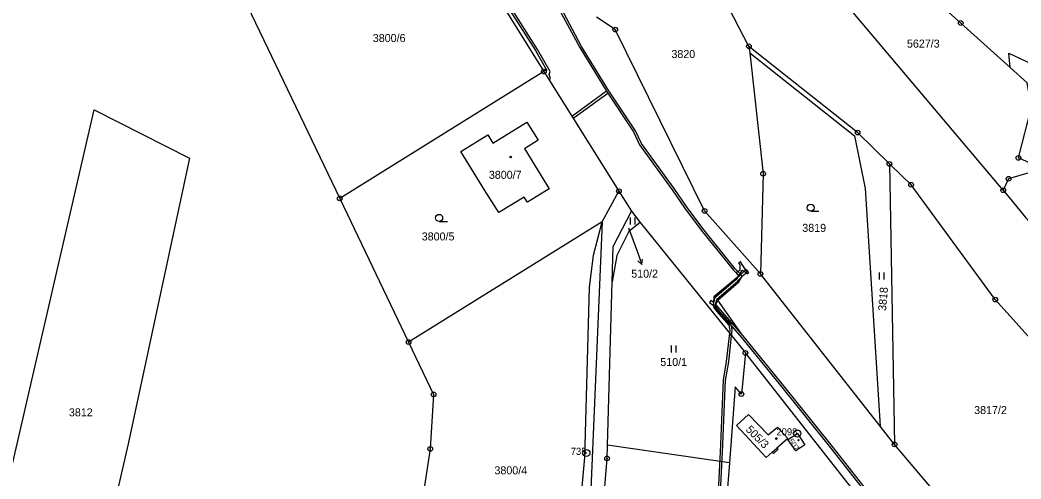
# Model space of a CAD drawing. Extents: x -644096 to -634268, y -1141430 to -1133463.
# Drawn here: x -640699.8 to -640487.2, y -1137603.8 to -1137506.2 of the extents above; entities that cross this region are included whole.
import ezdxf

# ---------------------------------------------------------------- set-up
doc = ezdxf.new("R2010")
doc.units = 0
for name, color, linetype in [('_CIVIL_CONSTRUCTION', 7, 'Continuous'), ('B_Hranice _3D', 7, 'Continuous'), ('M_Svah_Nasyp', 7, 'Continuous'), ('M_Svah_Zarez', 7, 'Continuous'), ('svrsek_osa_sjezdy', 7, 'Continuous'), ('svrsek_osa_VRT', 7, 'Continuous'), ('svrsek_popisy_VRT', 7, 'Continuous'), ('terminal_VRT', 7, 'Continuous')]:
    doc.layers.add(name, color=color, linetype=linetype)

msp = doc.modelspace()

# ---------------------------------------------------------------- linework, layer by layer
at = {"layer": '_CIVIL_CONSTRUCTION'}
for centre, radius in [((-640499.97, -1137506.88), 0.5), ((-640499.97, -1137506.88), 0.0303), ((-640573.37, -1137508.28), 0.5), ((-640573.37, -1137508.28), 0.0303), ((-640544.96, -1137511.84), 0.5), ((-640544.96, -1137511.84), 0.0303), ((-640588.52, -1137517.2), 0.5), ((-640588.52, -1137517.2), 0.0303), ((-640521.87, -1137530.18), 0.5), ((-640521.87, -1137530.18), 0.0303), ((-640515.13, -1137536.84), 0.5), ((-640515.13, -1137536.84), 0.0303), ((-640487.72, -1137535.55), 0.5), ((-640487.72, -1137535.55), 0.0303), ((-640541.95, -1137538.94), 0.5), ((-640541.95, -1137538.94), 0.0303), ((-640510.51, -1137541.27), 0.5), ((-640489.79, -1137539.99), 0.5), ((-640489.79, -1137539.99), 0.0303), ((-640572.6, -1137542.65), 0.5), ((-640572.6, -1137542.65), 0.0303), ((-640510.51, -1137541.27), 0.0303), ((-640490.94, -1137542.42), 0.5), ((-640490.94, -1137542.42), 0.0303), ((-640631.9, -1137544.15), 0.5), ((-640631.9, -1137544.15), 0.0303), ((-640554.39, -1137546.81), 0.5), ((-640554.39, -1137546.81), 0.0303), ((-640542.54, -1137560.2), 0.5), ((-640542.54, -1137560.2), 0.0303), ((-640492.62, -1137565.68), 0.5), ((-640492.62, -1137565.68), 0.0303), ((-640617.3, -1137574.69), 0.5), ((-640617.3, -1137574.69), 0.0303), ((-640545.72, -1137577), 0.5), ((-640545.72, -1137577), 0.0303), ((-640611.98, -1137585.82), 0.5), ((-640546.55, -1137585.75), 0.5), ((-640546.55, -1137585.75), 0.0303), ((-640611.98, -1137585.82), 0.0303), ((-640534.68, -1137594.14), 0.75), ((-640534.68, -1137594.14), 0.03), ((-640514.01, -1137596.46), 0.5), ((-640612.67, -1137597.4), 0.5), ((-640612.67, -1137597.4), 0.0303), ((-640579.49, -1137598.29), 0.75), ((-640579.49, -1137598.29), 0.03), ((-640514.01, -1137596.46), 0.0303), ((-640575.12, -1137599.42), 0.5), ((-640575.12, -1137599.42), 0.0303)]:
    msp.add_circle(centre, radius, dxfattribs=at)
at = {"layer": 'B_Hranice _3D'}
for points in [[(-640595.71, -1137504.26), (-640590.32, -1137512.76), (-640587.9, -1137517), (-640588.49, -1137517.02), (-640588.52, -1137517.2), (-640587.46, -1137518.9), (-640587.15, -1137518.7), (-640587.38, -1137517.83), (-640587.22, -1137517.16), (-640589.9, -1137512.5), (-640595.29, -1137504)], [(-640585.37, -1137503.86), (-640580.93, -1137512.11), (-640575.25, -1137521.39), (-640569.53, -1137530.02), (-640568.24, -1137532.75), (-640561.3, -1137542.31), (-640558.63, -1137546.18), (-640555.11, -1137550.91), (-640548.25, -1137559.45), (-640547.06, -1137560.64), (-640552.46, -1137565.07), (-640552.53, -1137566.28), (-640552.47, -1137566.95), (-640552.43, -1137567.35), (-640551.88, -1137568.14), (-640549.22, -1137571.12), (-640549.01, -1137572.18), (-640549.08, -1137572.82), (-640548.65, -1137573.37), (-640548.51, -1137572.16), (-640548.68, -1137571.29), (-640546.92, -1137573.3), (-640538.57, -1137583.56), (-640527.63, -1137597.19), (-640517.52, -1137610.05)], [(-640585.37, -1137503.86), (-640580.93, -1137512.11), (-640575.25, -1137521.39), (-640582.37, -1137526.58), (-640582.57, -1137526.7), (-640582.31, -1137527.12), (-640582.11, -1137527), (-640574.98, -1137521.82), (-640569.53, -1137530.02), (-640568.24, -1137532.75), (-640561.3, -1137542.31), (-640558.63, -1137546.18), (-640555.11, -1137550.91), (-640548.25, -1137559.45), (-640547.06, -1137560.64), (-640552.46, -1137565.07), (-640552.53, -1137566.28), (-640553.06, -1137565.86), (-640553.36, -1137566.26), (-640552.47, -1137566.95), (-640546.92, -1137573.3), (-640538.57, -1137583.56), (-640527.63, -1137597.19), (-640517.52, -1137610.05)], [(-640517.12, -1137609.75), (-640527.23, -1137596.89), (-640538.19, -1137583.24), (-640546.54, -1137572.98), (-640551.59, -1137565.77), (-640547.1, -1137561.88), (-640546.49, -1137560.82), (-640546.68, -1137560.31), (-640547.87, -1137559.13), (-640554.73, -1137550.59), (-640558.21, -1137545.9), (-640560.88, -1137542.03), (-640567.8, -1137532.49), (-640569.09, -1137529.78), (-640574.71, -1137521.33), (-640580.51, -1137511.85), (-640584.95, -1137503.6)], [(-640545.67, -1137559.38), (-640546.68, -1137560.31), (-640547.87, -1137559.13), (-640554.73, -1137550.59), (-640558.21, -1137545.9), (-640560.88, -1137542.03), (-640567.8, -1137532.49), (-640569.09, -1137529.78), (-640574.71, -1137521.33), (-640580.51, -1137511.85), (-640584.95, -1137503.6)], [(-640487.06, -1137645.3), (-640489.13, -1137643.47), (-640490.6, -1137641.59), (-640491.45, -1137640.46), (-640491.86, -1137640.27), (-640496.56, -1137634.97), (-640498.35, -1137634.11), (-640504.46, -1137627.49), (-640505.83, -1137625.5), (-640506.65, -1137624.49), (-640511.27, -1137618.95), (-640512.5, -1137617.22), (-640513.41, -1137614.17), (-640514.94, -1137612.71), (-640517.12, -1137609.75), (-640527.23, -1137596.89), (-640538.19, -1137583.24), (-640546.54, -1137572.98), (-640552.01, -1137566.72), (-640551.59, -1137565.77), (-640547.1, -1137561.88), (-640546.49, -1137560.82), (-640545.33, -1137559.74), (-640545.67, -1137559.38)]]:
    msp.add_lwpolyline(points, dxfattribs=at)
for points in [[(-640545.01, -1137559.9), (-640545.33, -1137559.46), (-640545.77, -1137559.17), (-640546.73, -1137557.63), (-640547.15, -1137557.89), (-640546.92, -1137558.26), (-640546.89, -1137559.52), (-640547.66, -1137559.93), (-640547.48, -1137560.26), (-640547.12, -1137560.52), (-640546.31, -1137559.41), (-640545.68, -1137559.83), (-640545.42, -1137560.19)], [(-640545.67, -1137559.38), (-640547.49, -1137561.13), (-640547.74, -1137561.47), (-640552.27, -1137565.34), (-640552.56, -1137566.77), (-640552.43, -1137567.35), (-640551.88, -1137568.14), (-640549.22, -1137571.12), (-640549.01, -1137572.18), (-640549.08, -1137572.82), (-640548.65, -1137573.37), (-640548.51, -1137572.16), (-640548.76, -1137570.88), (-640551.48, -1137567.82), (-640551.97, -1137567.15), (-640552.04, -1137566.77), (-640551.81, -1137565.6), (-640547.38, -1137561.81), (-640547.11, -1137561.47), (-640545.33, -1137559.74)], [(-640549.77, -1137578.81), (-640550.43, -1137582.83), (-640551.07, -1137598.09), (-640551.86, -1137613.51), (-640556.82, -1137647.62), (-640558.57, -1137666.41), (-640560, -1137686.48), (-640560.91, -1137694.7), (-640563.67, -1137695.47), (-640576.51, -1137693.45), (-640575.72, -1137694.09), (-640563.65, -1137695.99), (-640560.45, -1137695.1), (-640559.5, -1137686.52), (-640558.07, -1137666.45), (-640556.32, -1137647.68), (-640551.36, -1137613.55), (-640550.57, -1137598.11), (-640549.93, -1137582.89), (-640549.27, -1137578.87), (-640548.65, -1137573.37), (-640549.08, -1137572.82)]]:
    msp.add_lwpolyline(points, close=True, dxfattribs=at)
at = {"layer": 'M_Svah_Nasyp'}
msp.add_line((-640540.02, -1137598.09), (-640539.02, -1137597.22), dxfattribs=at)
at = {"layer": 'M_Svah_Zarez'}
for centre, radius in [((-640595.58, -1137535.37), 0.175), ((-640539.14, -1137595.2), 0.175), ((-640534.43, -1137595.54), 0.117)]:
    msp.add_circle(centre, radius, dxfattribs=at)
at = {"layer": 'svrsek_osa_sjezdy'}
for p, q in [((-640531.85, -1137546.89), (-640530.1, -1137546.89)), ((-640610.8, -1137549.05), (-640609.05, -1137549.05)), ((-640570.16, -1137549.74), (-640570.16, -1137548.24)), ((-640569.16, -1137549.74), (-640569.16, -1137548.24)), ((-640517.24, -1137561.42), (-640517.24, -1137559.92)), ((-640516.24, -1137561.42), (-640516.24, -1137559.92)), ((-640561.43, -1137576.91), (-640561.43, -1137575.41)), ((-640560.43, -1137576.91), (-640560.43, -1137575.41))]:
    msp.add_line(p, q, dxfattribs=at)
for centre in [(-640531.85, -1137546.14), (-640610.8, -1137548.3)]:
    msp.add_circle(centre, 0.75, dxfattribs=at)
at = {"layer": 'svrsek_popisy_VRT'}
for p, q in [((-640570.57, -1137550.45), (-640568.75, -1137555.37)), ((-640568.75, -1137555.37), (-640567.72, -1137558.19)), ((-640567.72, -1137558.19), (-640568.54, -1137557.42)), ((-640567.72, -1137558.19), (-640567.6, -1137557.08))]:
    msp.add_line(p, q, dxfattribs=at)
at = {"layer": 'terminal_VRT'}
for p, q in [((-640490.94, -1137542.42), (-640547.2, -1137475.72)), ((-640652.7, -1137500.65), (-640631.9, -1137544.15)), ((-640544.96, -1137511.84), (-640544.81, -1137513.24)), ((-640588.52, -1137517.2), (-640631.9, -1137544.15)), ((-640588.52, -1137517.2), (-640572.6, -1137542.65)), ((-640515.13, -1137536.84), (-640514.01, -1137596.46)), ((-640576.13, -1137549.11), (-640572.6, -1137542.65)), ((-640572.6, -1137542.65), (-640569.95, -1137546.91)), ((-640631.9, -1137544.15), (-640617.3, -1137574.69)), ((-640569.95, -1137546.91), (-640568.05, -1137549.26)), ((-640576.13, -1137549.11), (-640617.3, -1137574.69)), ((-640568.05, -1137549.26), (-640545.72, -1137577)), ((-640517.08, -1137592.55), (-640542.54, -1137560.2)), ((-640575.04, -1137596.64), (-640574.04, -1137561.9)), ((-640512.3, -1137619.49), (-640545.72, -1137577)), ((-640514.01, -1137596.46), (-640517.08, -1137592.55)), ((-640549.1, -1137600.38), (-640575.04, -1137596.64)), ((-640497.09, -1137616.4), (-640514.01, -1137596.46))]:
    msp.add_line(p, q, dxfattribs=at)
for points in [[(-640544.96, -1137511.84), (-640554.31, -1137493.73), (-640565.75, -1137475.24), (-640568.46, -1137472.15)], [(-640614.14, -1137476.23), (-640607.29, -1137488.59), (-640605.78, -1137489.49), (-640588.52, -1137517.2)], [(-640515.72, -1137492.72), (-640499.97, -1137506.88), (-640489.47, -1137516.32)], [(-640542.54, -1137560.2), (-640554.39, -1137546.81), (-640573.37, -1137508.28), (-640577.39, -1137505.61)], [(-640515.13, -1137536.84), (-640521.87, -1137530.18), (-640544.96, -1137511.84)], [(-640544.81, -1137513.24), (-640522.57, -1137530.89), (-640520.26, -1137542.03), (-640517.08, -1137592.55)], [(-640544.81, -1137513.24), (-640541.95, -1137538.94), (-640542.54, -1137560.2)], [(-640489.47, -1137516.32), (-640489.75, -1137513.29), (-640482.37, -1137516.77), (-640443.11, -1137524.4), (-640441.04, -1137525.49)], [(-640482.61, -1137537.85), (-640487.72, -1137535.55), (-640484.96, -1137524.77), (-640485.83, -1137519.6), (-640489.47, -1137516.32)], [(-640684.06, -1137525.35), (-640663.83, -1137535.62), (-640676.85, -1137596.34), (-640689.8, -1137652.7), (-640713.57, -1137652.87), (-640684.06, -1137525.35)], [(-640592.05, -1137544.98), (-640592.75, -1137543.89), (-640598.11, -1137547.19), (-640601.06, -1137542.45), (-640606.18, -1137534.21), (-640600.46, -1137530.66), (-640599.36, -1137532.42), (-640592.14, -1137527.98), (-640589.76, -1137531.81), (-640592.65, -1137533.6), (-640592.25, -1137534.24), (-640591, -1137536.27), (-640587.39, -1137542.11), (-640592.05, -1137544.98)], [(-640473.09, -1137587.43), (-640492.62, -1137565.68), (-640510.51, -1137541.27), (-640512.38, -1137539.47), (-640515.13, -1137536.84)], [(-640482.61, -1137537.85), (-640489.79, -1137539.99), (-640490.94, -1137542.42)], [(-640490.94, -1137542.42), (-640486.12, -1137548.28), (-640467.18, -1137569.19), (-640450.33, -1137589.66), (-640449.14, -1137590.3), (-640435, -1137601.49)], [(-640574.04, -1137561.9), (-640573.82, -1137554.39), (-640569.95, -1137546.91)], [(-640583.1, -1137637.6), (-640581.58, -1137619.82), (-640584.2, -1137616.42), (-640594.65, -1137614.91), (-640593.87, -1137609.46), (-640584.22, -1137610.85), (-640580.6, -1137607.82), (-640579.87, -1137599.2), (-640578.82, -1137563.07), (-640577.96, -1137556.23), (-640576.13, -1137549.11)], [(-640576.13, -1137549.11), (-640578.59, -1137606.01), (-640581.75, -1137637.79)], [(-640568.05, -1137549.26), (-640570.46, -1137551.21), (-640573.04, -1137556.29), (-640574.04, -1137561.9)], [(-640617.3, -1137574.69), (-640611.98, -1137585.82), (-640612.67, -1137597.4), (-640618.05, -1137632.56)], [(-640545.72, -1137577), (-640546.55, -1137585.75), (-640547.86, -1137584.24), (-640549.1, -1137600.38)], [(-640540.02, -1137598.09), (-640541.28, -1137599.2), (-640547.63, -1137592.43), (-640545.04, -1137590.09), (-640540.89, -1137594.45), (-640538.91, -1137592.76), (-640536.67, -1137595.17), (-640539.02, -1137597.22), (-640538.78, -1137597.48), (-640539.78, -1137598.36), (-640540.02, -1137598.09)], [(-640536.7, -1137595.43), (-640534.68, -1137594.14), (-640533.11, -1137596.57), (-640534.99, -1137597.83), (-640536.7, -1137595.43)], [(-640578.31, -1137638.29), (-640575.12, -1137599.42), (-640575.04, -1137596.64)], [(-640549.1, -1137600.38), (-640549.71, -1137608.31), (-640554.14, -1137641.77)]]:
    msp.add_lwpolyline(points, dxfattribs=at)

# ---------------------------------------------------------------- texts
at = {"layer": '_CIVIL_CONSTRUCTION'}
for s, p in [('2098', (-640539.13, -1137594.52)), ('735', (-640582.83, -1137598.67))]:
    msp.add_text(s, height=1.5, dxfattribs=at).set_placement(p)
at = {"layer": 'svrsek_osa_VRT'}
for s, p in [('3800/6', (-640624.89, -1137510.92)), ('5627/3', (-640511.39, -1137512.11)), ('3820', (-640561.44, -1137514.33)), ('3800/7', (-640600.23, -1137540)), ('3819', (-640533.63, -1137551.27)), ('3800/5', (-640614.49, -1137553.1)), ('510/2', (-640569.98, -1137561.01)), ('510/1', (-640563.8, -1137579.78)), ('3812', (-640689.46, -1137590.49)), ('3817/2', (-640497.11, -1137590)), ('3800/4', (-640599.04, -1137602.81))]:
    msp.add_text(s, height=1.7, dxfattribs=at).set_placement(p)
for s, height, rotation, p in [('3818', 1.7, 85, (-640515.85, -1137568.13)), ('505/3', 1.7, 315, (-640545.77, -1137593.44)), ('507', 1.19, 305, (-640536.66, -1137595.76))]:
    msp.add_text(s, height=height, rotation=rotation, dxfattribs=at).set_placement(p)

doc.saveas('drawing.dxf')
